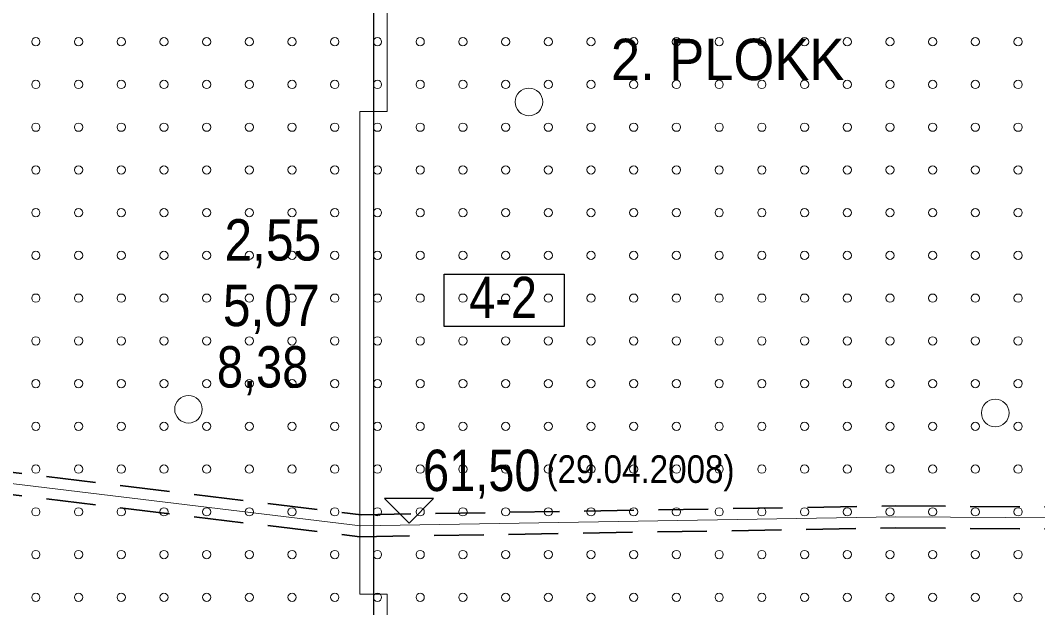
# Model space of a CAD drawing. Extents: x 640104 to 640970, y 6442278 to 6442689.
# Drawn here: x 640245.1 to 640319, y 6442547 to 6442589.6 of the extents above; entities that cross this region are included whole.
import ezdxf
from ezdxf.enums import TextEntityAlignment as Align

# ---------------------------------------------------------------- set-up
doc = ezdxf.new("R2010")
doc.units = 0
doc.header["$LTSCALE"] = 1.2
doc.linetypes.add('MEDIUM_DASHED', pattern=[4.5, 3, -1.5])
for name, color, linetype, lineweight in [('32', 7, 'Continuous', 25), ('33', 7, 'Continuous', 13), ('34', 7, 'Continuous', 25), ('35', 7, 'Continuous', 35), ('43', 7, 'Continuous', 13), ('47', 7, 'Continuous', 13)]:
    doc.layers.add(name, color=color, linetype=linetype, lineweight=lineweight)

msp = doc.modelspace()

# ---------------------------------------------------------------- linework, layer by layer
at = {"layer": '32'}
msp.add_line((640270.76, 6442623), (640270.76, 6442501), dxfattribs=at)
at = {"layer": '33'}
for points in [[(640271.76, 6442583), (640271.76, 6442618.88), (640270.76, 6442619), (640270.76, 6442583)], [(640269.76, 6442583), (640269.76, 6442548), (640270.76, 6442548), (640270.76, 6442583)], [(640271.76, 6442523.08), (640271.76, 6442548), (640270.76, 6442548), (640270.76, 6442523.04)]]:
    msp.add_lwpolyline(points, close=True, dxfattribs=at)
at = {"layer": '33', "lineweight": 25}
msp.add_lwpolyline([(640275.89, 6442571.22), (640284.6, 6442571.22), (640284.6, 6442567.42), (640275.89, 6442567.42)], close=True, dxfattribs=at)
at = {"layer": '34', "lineweight": 13}
msp.add_lwpolyline([(640136.43, 6442567), (640170.34, 6442565), (640269.82, 6442552.96), (640308.67, 6442553.6), (640395.86, 6442553.07), (640412.35, 6442552.95), (640418.42, 6442552.96)], dxfattribs=at)
at = {"layer": '34'}
msp.add_lwpolyline([(640271.55, 6442554.95), (640273.34, 6442553.14), (640275.11, 6442554.94)], close=True, dxfattribs=at)
at = {"layer": '35', "linetype": 'MEDIUM_DASHED'}
for points in [[(640171.96, 6442565.61), (640269.86, 6442553.76), (640308.67, 6442554.4), (640395.87, 6442553.87), (640403.06, 6442553.81)], [(640171.96, 6442564), (640269.77, 6442552.16), (640308.67, 6442552.8), (640395.86, 6442552.27), (640403.06, 6442552.21)]]:
    msp.add_lwpolyline(points, dxfattribs=at)
at = {"layer": '43'}
for centre in [(640246.249, 6442588.073), (640249.349, 6442588.073), (640252.449, 6442588.073), (640255.549, 6442588.073), (640258.649, 6442588.073), (640261.749, 6442588.073), (640264.849, 6442588.073), (640267.949, 6442588.073), (640271.049, 6442588.073), (640274.149, 6442588.073), (640277.249, 6442588.073), (640280.349, 6442588.073), (640283.449, 6442588.073), (640286.549, 6442588.073), (640289.649, 6442588.073), (640292.749, 6442588.073), (640295.849, 6442588.073), (640298.949, 6442588.073), (640302.049, 6442588.073), (640305.149, 6442588.073), (640308.249, 6442588.073), (640311.349, 6442588.073), (640314.449, 6442588.073), (640317.549, 6442588.073), (640246.249, 6442584.973), (640249.349, 6442584.973), (640252.449, 6442584.973), (640255.549, 6442584.973), (640258.649, 6442584.973), (640261.749, 6442584.973), (640264.849, 6442584.973), (640267.949, 6442584.973), (640271.049, 6442584.973), (640274.149, 6442584.973), (640277.249, 6442584.973), (640280.349, 6442584.973), (640283.449, 6442584.973), (640286.549, 6442584.973), (640289.649, 6442584.973), (640292.749, 6442584.973), (640295.849, 6442584.973), (640298.949, 6442584.973), (640302.049, 6442584.973), (640305.149, 6442584.973), (640308.249, 6442584.973), (640311.349, 6442584.973), (640314.449, 6442584.973), (640317.549, 6442584.973), (640246.249, 6442581.873), (640249.349, 6442581.873), (640252.449, 6442581.873), (640255.549, 6442581.873), (640258.649, 6442581.873), (640261.749, 6442581.873), (640264.849, 6442581.873), (640267.949, 6442581.873), (640271.049, 6442581.873), (640274.149, 6442581.873), (640277.249, 6442581.873), (640280.349, 6442581.873), (640283.449, 6442581.873), (640286.549, 6442581.873), (640289.649, 6442581.873), (640292.749, 6442581.873), (640295.849, 6442581.873), (640298.949, 6442581.873), (640302.049, 6442581.873), (640305.149, 6442581.873), (640308.249, 6442581.873), (640311.349, 6442581.873), (640314.449, 6442581.873), (640317.549, 6442581.873), (640246.249, 6442578.773), (640249.349, 6442578.773), (640252.449, 6442578.773), (640255.549, 6442578.773), (640258.649, 6442578.773), (640261.749, 6442578.773), (640264.849, 6442578.773), (640267.949, 6442578.773), (640271.049, 6442578.773), (640274.149, 6442578.773), (640277.249, 6442578.773), (640280.349, 6442578.773), (640283.449, 6442578.773), (640286.549, 6442578.773), (640289.649, 6442578.773), (640292.749, 6442578.773), (640295.849, 6442578.773), (640298.949, 6442578.773), (640302.049, 6442578.773), (640305.149, 6442578.773), (640308.249, 6442578.773), (640311.349, 6442578.773), (640314.449, 6442578.773), (640317.549, 6442578.773), (640246.249, 6442575.673), (640249.349, 6442575.673), (640252.449, 6442575.673), (640255.549, 6442575.673), (640258.649, 6442575.673), (640261.749, 6442575.673), (640264.849, 6442575.673), (640267.949, 6442575.673), (640271.049, 6442575.673), (640274.149, 6442575.673), (640277.249, 6442575.673), (640280.349, 6442575.673), (640283.449, 6442575.673), (640286.549, 6442575.673), (640289.649, 6442575.673), (640292.749, 6442575.673), (640295.849, 6442575.673), (640298.949, 6442575.673), (640302.049, 6442575.673), (640305.149, 6442575.673), (640308.249, 6442575.673), (640311.349, 6442575.673), (640314.449, 6442575.673), (640317.549, 6442575.673), (640246.249, 6442572.573), (640249.349, 6442572.573), (640252.449, 6442572.573), (640255.549, 6442572.573), (640258.649, 6442572.573), (640261.749, 6442572.573), (640264.849, 6442572.573), (640267.949, 6442572.573), (640271.049, 6442572.573), (640274.149, 6442572.573), (640277.249, 6442572.573), (640280.349, 6442572.573), (640283.449, 6442572.573), (640286.549, 6442572.573), (640289.649, 6442572.573), (640292.749, 6442572.573), (640295.849, 6442572.573), (640298.949, 6442572.573), (640302.049, 6442572.573), (640305.149, 6442572.573), (640308.249, 6442572.573), (640311.349, 6442572.573), (640314.449, 6442572.573), (640317.549, 6442572.573), (640246.249, 6442569.473), (640249.349, 6442569.473), (640252.449, 6442569.473), (640255.549, 6442569.473), (640258.649, 6442569.473), (640261.749, 6442569.473), (640264.849, 6442569.473), (640267.949, 6442569.473), (640271.049, 6442569.473), (640274.149, 6442569.473), (640277.249, 6442569.473), (640280.349, 6442569.473), (640283.449, 6442569.473), (640286.549, 6442569.473), (640289.649, 6442569.473), (640292.749, 6442569.473), (640295.849, 6442569.473), (640298.949, 6442569.473), (640302.049, 6442569.473), (640305.149, 6442569.473), (640308.249, 6442569.473), (640311.349, 6442569.473), (640314.449, 6442569.473), (640317.549, 6442569.473), (640246.249, 6442566.373), (640249.349, 6442566.373), (640252.449, 6442566.373), (640255.549, 6442566.373), (640258.649, 6442566.373), (640261.749, 6442566.373), (640264.849, 6442566.373), (640267.949, 6442566.373), (640271.049, 6442566.373), (640274.149, 6442566.373), (640277.249, 6442566.373), (640280.349, 6442566.373), (640283.449, 6442566.373), (640286.549, 6442566.373), (640289.649, 6442566.373), (640292.749, 6442566.373), (640295.849, 6442566.373), (640298.949, 6442566.373), (640302.049, 6442566.373), (640305.149, 6442566.373), (640308.249, 6442566.373), (640311.349, 6442566.373), (640314.449, 6442566.373), (640317.549, 6442566.373), (640246.249, 6442563.273), (640249.349, 6442563.273), (640252.449, 6442563.273), (640255.549, 6442563.273), (640258.649, 6442563.273), (640261.749, 6442563.273), (640264.849, 6442563.273), (640267.949, 6442563.273), (640271.049, 6442563.273), (640274.149, 6442563.273), (640277.249, 6442563.273), (640280.349, 6442563.273), (640283.449, 6442563.273), (640286.549, 6442563.273), (640289.649, 6442563.273), (640292.749, 6442563.273), (640295.849, 6442563.273), (640298.949, 6442563.273), (640302.049, 6442563.273), (640305.149, 6442563.273), (640308.249, 6442563.273), (640311.349, 6442563.273), (640314.449, 6442563.273), (640317.549, 6442563.273), (640246.249, 6442560.173), (640249.349, 6442560.173), (640252.449, 6442560.173), (640255.549, 6442560.173), (640258.649, 6442560.173), (640261.749, 6442560.173), (640264.849, 6442560.173), (640267.949, 6442560.173), (640271.049, 6442560.173), (640274.149, 6442560.173), (640277.249, 6442560.173), (640280.349, 6442560.173), (640283.449, 6442560.173), (640286.549, 6442560.173), (640289.649, 6442560.173), (640292.749, 6442560.173), (640295.849, 6442560.173), (640298.949, 6442560.173), (640302.049, 6442560.173), (640305.149, 6442560.173), (640308.249, 6442560.173), (640311.349, 6442560.173), (640314.449, 6442560.173), (640317.549, 6442560.173), (640246.249, 6442557.073), (640249.349, 6442557.073), (640252.449, 6442557.073), (640255.549, 6442557.073), (640258.649, 6442557.073), (640261.749, 6442557.073), (640264.849, 6442557.073), (640267.949, 6442557.073), (640271.049, 6442557.073), (640274.149, 6442557.073), (640277.249, 6442557.073), (640280.349, 6442557.073), (640283.449, 6442557.073), (640286.549, 6442557.073), (640289.649, 6442557.073), (640292.749, 6442557.073), (640295.849, 6442557.073), (640298.949, 6442557.073), (640302.049, 6442557.073), (640305.149, 6442557.073), (640308.249, 6442557.073), (640311.349, 6442557.073), (640314.449, 6442557.073), (640317.549, 6442557.073), (640246.249, 6442553.973), (640249.349, 6442553.973), (640252.449, 6442553.973), (640255.549, 6442553.973), (640258.649, 6442553.973), (640261.749, 6442553.973), (640264.849, 6442553.973), (640267.949, 6442553.973), (640271.049, 6442553.973), (640274.149, 6442553.973), (640277.249, 6442553.973), (640280.349, 6442553.973), (640283.449, 6442553.973), (640286.549, 6442553.973), (640289.649, 6442553.973), (640292.749, 6442553.973), (640295.849, 6442553.973), (640298.949, 6442553.973), (640302.049, 6442553.973), (640305.149, 6442553.973), (640308.249, 6442553.973), (640311.349, 6442553.973), (640314.449, 6442553.973), (640317.549, 6442553.973), (640246.249, 6442550.873), (640249.349, 6442550.873), (640252.449, 6442550.873), (640255.549, 6442550.873), (640258.649, 6442550.873), (640261.749, 6442550.873), (640264.849, 6442550.873), (640267.949, 6442550.873), (640271.049, 6442550.873), (640274.149, 6442550.873), (640277.249, 6442550.873), (640280.349, 6442550.873), (640283.449, 6442550.873), (640286.549, 6442550.873), (640289.649, 6442550.873), (640292.749, 6442550.873), (640295.849, 6442550.873), (640298.949, 6442550.873), (640302.049, 6442550.873), (640305.149, 6442550.873), (640308.249, 6442550.873), (640311.349, 6442550.873), (640314.449, 6442550.873), (640317.549, 6442550.873), (640246.249, 6442547.773), (640249.349, 6442547.773), (640252.449, 6442547.773), (640255.549, 6442547.773), (640258.649, 6442547.773), (640261.749, 6442547.773), (640264.849, 6442547.773), (640267.949, 6442547.773), (640271.049, 6442547.773), (640274.149, 6442547.773), (640277.249, 6442547.773), (640280.349, 6442547.773), (640283.449, 6442547.773), (640286.549, 6442547.773), (640289.649, 6442547.773), (640292.749, 6442547.773), (640295.849, 6442547.773), (640298.949, 6442547.773), (640302.049, 6442547.773), (640305.149, 6442547.773), (640308.249, 6442547.773), (640311.349, 6442547.773), (640314.449, 6442547.773), (640317.549, 6442547.773)]:
    msp.add_circle(centre, 0.3, dxfattribs=at)
at = {"layer": '47'}
for centre in [(640282.043, 6442583.706), (640257.329, 6442561.41), (640315.891, 6442561.141)]:
    msp.add_circle(centre, 1, dxfattribs=at)

# ---------------------------------------------------------------- texts
at = {"layer": '33'}
for s, width, p in [('2,55', 0.9, (640263.455, 6442572.2)), ('4-2', 0.85, (640280.165, 6442568.02)), ('5,07', 0.9, (640263.34, 6442567.44)), ('8,38', 0.85, (640262.71, 6442562.99))]:
    msp.add_text(s, height=3, dxfattribs=dict(at, width=width)).set_placement(p, align=Align.CENTER)
at = {"layer": '34'}
for s, height, width, p in [('61,50', 3, 0.85, (640278.62, 6442555.48)), ('(29.04.2008)', 2, 0.9, (640290.14, 6442556.07))]:
    msp.add_text(s, height=height, dxfattribs=dict(at, width=width)).set_placement(p, align=Align.CENTER)
at = {"layer": '35', "width": 0.95}
msp.add_text('2. PLOKK', height=3, dxfattribs=at).set_placement((640296.465, 6442585.29), align=Align.CENTER)

doc.saveas('drawing.dxf')
